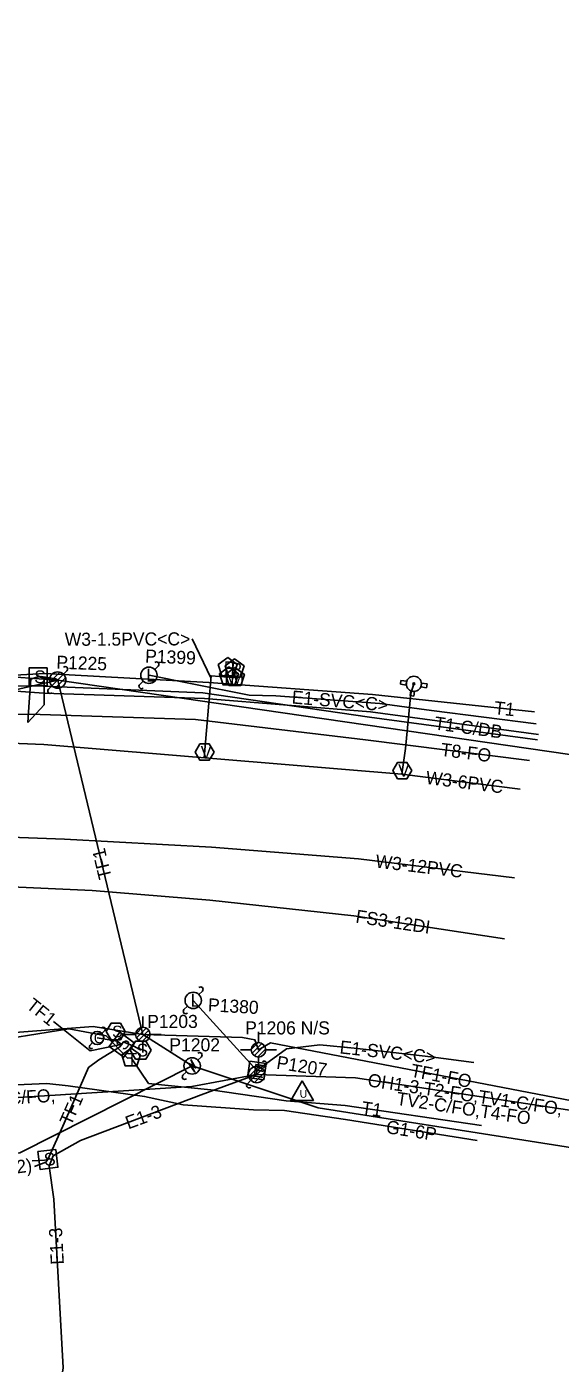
# Model space of a CAD drawing. Extents: x 2336688 to 2352634, y 362473 to 369571.
# Drawn here: x 2352182.9 to 2352345.9, y 368798.3 to 369206.7 of the extents above; entities that cross this region are included whole.
import ezdxf

# ---------------------------------------------------------------- set-up
doc = ezdxf.new("R2010")
doc.units = 0
for name, color, linetype in [('RD_EX_DV_Prop', 7, 'Continuous'), ('RD_EX_DV_TX_Prop', 7, 'Continuous'), ('RD_EX_RW', 7, 'Continuous'), ('RD_EX_RW_TX', 7, 'Continuous'), ('RD_HC_CL_Rel', 7, 'Continuous'), ('RD_HC_Data_Tic', 7, 'Continuous'), ('RD_PD_CstnLmt', 7, 'Continuous'), ('RD_PD_Final_TrvlWay', 7, 'Continuous'), ('RD_PD_FOC', 7, 'Continuous'), ('RD_PD_PatLn2', 7, 'Continuous'), ('RD_PD_PatLn3', 7, 'Continuous'), ('RD_PD_PatLn4', 7, 'Continuous'), ('RD_SHT_ShtClip', 7, 'Continuous'), ('RD_Sketch1', 7, 'Continuous'), ('RD_Sketch2', 7, 'Continuous'), ('RD_Sketch5', 7, 'Continuous'), ('RD_Sketch8', 7, 'Continuous')]:
    doc.layers.add(name, color=color, linetype=linetype)

msp = doc.modelspace()

# ---------------------------------------------------------------- linework, layer by layer
at = {"layer": 'RD_EX_RW_TX'}
for points in [[(2352017.22, 369198.89), (2352037.02, 369199.92), (2352057.29, 369203.53), (2352058.07, 369204.44), (2352059.01, 369204.47), (2352060.05, 369204.49), (2352061.29, 369203.9), (2352068.47, 369206.66), (2352070.73, 369196.74), (2352081.19, 369147.72), (2352093.25, 369098.87), (2352105.47, 369036.02), (2352109, 369016.44), (2352109.72, 369006.36), (2352146.03, 369006.1), (2352188.1, 369003.03), (2352237.18, 369001.37), (2352287.91, 368997.38), (2352339.27, 368990.42)], [(2352338.07, 368997.32), (2352288.54, 369002.61), (2352238.52, 369006.32), (2352188.44, 369009.03), (2352146.1, 369006.66), (2352112.83, 369007.85), (2352101.04, 369009.02), (2352100.18, 369013.02), (2352099.24, 369013.18), (2352099.24, 369013.18), (2352097.56, 369004.44), (2352066.15, 368999.94), (2352042.65, 368996), (2351987.9, 368984.55), (2351939.24, 368974.38), (2351880.64, 368964.81), (2351835.05, 368955.54), (2351792.2, 368945.42), (2351768.45, 368940.51), (2351765.56, 368959.31), (2351765.09, 368961.33)], [(2351880.81, 368963.77), (2351939.3, 368973.2), (2351988.46, 368983.33), (2352042.97, 368994.86), (2352066.53, 368998.78), (2352097.52, 369003.45), (2352112.86, 369004.95), (2352145.97, 369005.39), (2352187.91, 369005.14), (2352236.72, 369003.16), (2352287.61, 368995.73), (2352338.92, 368988.74)], [(2351885, 368956.88), (2351939.56, 368969.89), (2351988.67, 368980.31), (2352043.04, 368991.24), (2352066.63, 368994.3), (2352086.86, 368995.79), (2352106.62, 368995.87), (2352143.1, 368996.58), (2352187.05, 368996.47), (2352234.49, 368995.02), (2352286.43, 368988.83), (2352336.53, 368982.42)], [(2351854.2, 368855.12), (2351907.65, 368859.27), (2351954.44, 368863.43), (2352008.74, 368870.56), (2352052.2, 368876.14), (2352056.52, 368876.05), (2352074.96, 368878.4), (2352092.6, 368880.26), (2352100.36, 368883.74), (2352107.85, 368885.7), (2352121.63, 368887.01), (2352147.59, 368892.36), (2352167.89, 368895.99), (2352195.79, 368900.53), (2352207.22, 368898.3), (2352213.66, 368891.52), (2352214.78, 368891.59), (2352220.15, 368883.78), (2352239.13, 368881.83), (2352262.16, 368878.52), (2352280.21, 368877.05), (2352321.83, 368870.98)]]:
    msp.add_lwpolyline(points, dxfattribs=at)
msp.add_lwpolyline([(2352214.78, 368894.59), (2352211.92, 368892.51), (2352213.01, 368889.16), (2352216.54, 368889.16), (2352217.63, 368892.51)], close=True, dxfattribs=at)
at = {"layer": 'RD_HC_CL_Rel'}
msp.add_lwpolyline([(2351856.12, 368845.07), (2351908.31, 368852.47), (2351954.47, 368856.39), (2351989.24, 368859.76), (2352009.1, 368863.3), (2352075.82, 368872.25), (2352088.74, 368873.22), (2352101.35, 368874.84), (2352111.2, 368876.2), (2352126.61, 368879.82), (2352147.61, 368881.9), (2352189.06, 368883.81), (2352195.59, 368883.03), (2352218.93, 368879.85), (2352230.72, 368877.21), (2352252.22, 368875.78), (2352261.65, 368875.52), (2352280.31, 368872.79), (2352320.53, 368866.38)], dxfattribs=at)
at = {"layer": 'RD_HC_Data_Tic'}
for p, q in [((2352189.96, 369006.41), (2352193.03, 369009.47)), ((2352190.61, 369005.29), (2352194.15, 369008.82)), ((2352194.15, 369008.82), (2352195.21, 369009.88)), ((2352222.02, 369010.27), (2352223.08, 369011.33)), ((2352189.55, 369004.23), (2352190.61, 369005.29)), ((2352191.73, 369004.64), (2352194.79, 369007.7)), ((2352217.42, 369005.68), (2352218.48, 369006.74)), ((2352235.53, 368910.94), (2352236.59, 368912.01)), ((2352230.94, 368906.35), (2352232, 368907.41)), ((2352218.4, 368904.25), (2352218.4, 368900.96)), ((2352205.87, 368899.1), (2352206.72, 368899.95)), ((2352212.88, 368898.74), (2352216.19, 368898.74)), ((2352216.19, 368898.88), (2352218.27, 368900.96)), ((2352216.44, 368897.71), (2352219.44, 368900.71)), ((2352217.1, 368896.96), (2352220.2, 368900.05)), ((2352218.11, 368896.55), (2352220.6, 368899.04)), ((2352220.62, 368898.75), (2352223.93, 368898.75)), ((2352253.71, 368899.56), (2352253.71, 368896.27)), ((2352202.19, 368895.42), (2352203.04, 368896.27)), ((2352218.4, 368896.53), (2352218.4, 368893.25)), ((2352248.18, 368894.05), (2352251.49, 368894.05)), ((2352251.5, 368894.19), (2352253.58, 368896.27)), ((2352251.75, 368893.02), (2352254.74, 368896.02)), ((2352252.4, 368892.27), (2352255.5, 368895.36)), ((2352253.41, 368891.86), (2352255.91, 368894.36)), ((2352255.93, 368894.06), (2352259.24, 368894.07)), ((2352235.22, 368890.91), (2352236.28, 368891.97)), ((2352253.71, 368891.84), (2352253.71, 368888.56)), ((2352230.62, 368886.31), (2352231.68, 368887.37)), ((2352250.72, 368885.87), (2352253.78, 368888.94)), ((2352251.37, 368884.75), (2352254.9, 368888.29)), ((2352252.49, 368884.11), (2352255.55, 368887.17)), ((2352254.9, 368888.29), (2352255.96, 368889.35)), ((2352250.31, 368883.69), (2352251.37, 368884.75))]:
    msp.add_line(p, q, dxfattribs=at)
msp.add_lwpolyline([(2352233.06, 368891.15), (2352233.88, 368889.14), (2352232.43, 368889.94), (2352234.3, 368887.26), (2352234.3, 368887.26), (2352233.1, 368889.35), (2352234.48, 368888.55)], close=True, dxfattribs=at)
for centre, radius in [((2352192.38, 369007.05), 2.5), ((2352220.25, 369008.51), 2.5), ((2352233.76, 368909.18), 2.5), ((2352204.46, 368897.69), 2), ((2352218.4, 368898.75), 2.22), ((2352253.71, 368894.06), 2.22), ((2352233.45, 368889.14), 2.5), ((2352253.13, 368886.52), 2.5)]:
    msp.add_circle(centre, radius, dxfattribs=at)
for centre, radius, start, end in [((2352222.55, 369011.86), 0.75, 315, 135), ((2352194.68, 369010.41), 0.75, 315, 135), ((2352190.08, 369003.7), 0.75, 135, 315), ((2352217.95, 369005.15), 0.75, 135, 315), ((2352236.06, 368912.54), 0.75, 315, 135), ((2352231.47, 368905.82), 0.75, 135, 315), ((2352206.3, 368900.37), 0.6, 315, 135), ((2352202.62, 368895), 0.6, 135, 315), ((2352235.75, 368892.5), 0.75, 315, 135), ((2352255.43, 368889.88), 0.75, 315, 135), ((2352231.15, 368885.78), 0.75, 135, 315), ((2352250.84, 368883.16), 0.75, 135, 315)]:
    msp.add_arc(centre, radius, start, end, dxfattribs=at)
at = {"layer": 'RD_PD_CstnLmt'}
msp.add_line((2352233.4, 369019.65), (2352239.15, 369007.75), dxfattribs=at)
at = {"layer": 'RD_PD_Final_TrvlWay'}
for points in [[(2352220.29, 369008.57), (2352233.42, 369005.94), (2352250.85, 369002.45), (2352259.02, 369002.26), (2352290.75, 368999.87), (2352306.52, 368997.78), (2352338.57, 368993.64)], [(2352253.22, 368887.73), (2352233.76, 368909.18), (2352233.81, 368909.18)], [(2352218.4, 368898.75), (2352248.79, 368897.87), (2352252.62, 368897.13), (2352253.71, 368894.06), (2352257.36, 368896.22), (2352357.47, 368876.97), (2352386.01, 368866.51)], [(2352253.13, 368886.52), (2352253.22, 368887.73), (2352262.26, 368894.32), (2352272.48, 368895.58), (2352282.96, 368894.53), (2352294.85, 368893.28), (2352306.35, 368891.96), (2352319.46, 368890.19)], [(2352253.13, 368886.52), (2352236.2, 368880.33), (2352199.36, 368866.35), (2352190.99, 368861.65), (2352189.74, 368858.57), (2352191.19, 368848.42), (2352194.01, 368796.93), (2352186.25, 368745.32), (2352172.04, 368697.96), (2352173.22, 368647.74), (2352174.91, 368598.79), (2352184.51, 368549.35), (2352193.88, 368501.9), (2352208.42, 368452.8), (2352218.56, 368402.62)], [(2352253.13, 368886.52), (2352283.32, 368885.51), (2352356.87, 368874.44), (2352386.01, 368866.51)]]:
    msp.add_lwpolyline(points, dxfattribs=at)
msp.add_lwpolyline([(2352256.06, 368889.84), (2352251.11, 368890.57), (2352250.38, 368885.63), (2352255.32, 368884.89)], close=True, dxfattribs=at)
at = {"layer": 'RD_PD_FOC'}
for p, q in [((2352183.25, 368994.07), (2352183.67, 369000.32)), ((2352188.28, 368999.49), (2352183.25, 368994.07))]:
    msp.add_line(p, q, dxfattribs=at)
at = {"layer": 'RD_PD_PatLn3'}
msp.add_lwpolyline([(2352267.05, 368884.63), (2352263.58, 368878.63), (2352270.51, 368878.63)], close=True, dxfattribs=at)
at = {"layer": 'RD_SHT_ShtClip'}
for p, q in [((2352192.38, 369007.05), (2352586.08, 368949.9)), ((2352192.38, 369007.05), (2352218.4, 368898.75)), ((2352218.4, 368898.75), (2352233.45, 368889.14))]:
    msp.add_line(p, q, dxfattribs=at)
for points in [[(2352088.13, 369009.76), (2352108.15, 369010.14), (2352172.41, 369008.48), (2352192.38, 369007.05)], [(2352192.38, 369007.05), (2352172.65, 369002.58), (2352092.75, 368996.67), (2352072.58, 368998.19)], [(2352091.68, 368889.02), (2352106.36, 368893.74), (2352203.18, 368901.17), (2352218.4, 368898.75)], [(2351832.35, 368849.22), (2351889.18, 368833.54), (2352180.82, 368862.57), (2352233.45, 368889.14)], [(2352105.46, 368877.27), (2352125.58, 368876.07), (2352233.33, 368882.82), (2352253.13, 368886.52)], [(2352233.45, 368889.14), (2352271.93, 368876.31), (2352518.65, 368837.57), (2352559.21, 368838)]]:
    msp.add_lwpolyline(points, dxfattribs=at)
at = {"layer": 'RD_Sketch2'}
for p, q in [((2352297.19, 369006.92), (2352297.04, 369005.77)), ((2352297.04, 369005.77), (2352298.88, 369005.53)), ((2352298.99, 369006.68), (2352297.19, 369006.92)), ((2352303.27, 369004.95), (2352305.06, 369004.71)), ((2352305.21, 369005.86), (2352303.47, 369006.09)), ((2352305.06, 369004.71), (2352305.21, 369005.86)), ((2352300.25, 369003.77), (2352300.06, 369002.29)), ((2352300.06, 369002.29), (2352301.2, 369002.14)), ((2352301.2, 369002.14), (2352301.39, 369003.6))]:
    msp.add_line(p, q, dxfattribs=at)
for points in [[(2352244.3, 369013.9), (2352241.4, 369011.79), (2352242.51, 369008.38), (2352246.09, 369008.38), (2352247.2, 369011.79)], [(2352246.4, 369013.48), (2352243.5, 369011.37), (2352244.61, 369007.96), (2352248.19, 369007.96), (2352249.3, 369011.37)], [(2352244.67, 369011.07), (2352241.77, 369008.96), (2352242.88, 369005.55), (2352246.46, 369005.55), (2352247.57, 369008.96)], [(2352246.5, 369010.87), (2352243.6, 369008.77), (2352244.71, 369005.36), (2352248.29, 369005.36), (2352249.4, 369008.77)], [(2352240.14, 368985.03), (2352238.69, 368987.53), (2352235.81, 368987.53), (2352234.36, 368985.03), (2352235.81, 368982.53), (2352238.69, 368982.53)], [(2352300.51, 368979.38), (2352299.07, 368981.87), (2352296.18, 368981.87), (2352294.74, 368979.38), (2352296.18, 368976.88), (2352299.07, 368976.88)]]:
    msp.add_lwpolyline(points, close=True, dxfattribs=at)
for points in [[(2352237.11, 368983.31), (2352239.2, 369008.35), (2352244.33, 369007.93)], [(2352297.48, 368978.27), (2352298.57, 368986.11), (2352300.25, 369002.94), (2352301.17, 369005.9)], [(2352089.34, 368987.1), (2352123.62, 368989.01), (2352145.53, 368989.09), (2352188.15, 368987.39), (2352297.48, 368978.27), (2352333.69, 368973.72)], [(2352331.96, 368946.65), (2352284.3, 368952.4), (2352239.4, 368955.94), (2352194.47, 368958.42), (2352147.57, 368960.14), (2352120.89, 368957.46), (2352095.02, 368954.62), (2352046.17, 368949), (2351993.84, 368939.17), (2351944.25, 368929.23), (2351897.87, 368918.99), (2351839.37, 368906.5)]]:
    msp.add_lwpolyline(points, dxfattribs=at)
for radius in [2.31, 0.289]:
    msp.add_circle((2352301.17, 369005.9), radius, dxfattribs=at)
for start, end in [(160.1572, 189.1335), (335.8109, 4.7872), (246.7177, 275.6849)]:
    msp.add_arc((2352301.17, 369005.9), 2.31, start, end, dxfattribs=at)
at = {"layer": 'RD_Sketch5'}
msp.add_lwpolyline([(2351852.53, 368877.54), (2351904.23, 368891.75), (2351948.35, 368906.63), (2351997.09, 368925.32), (2352048.14, 368938.94), (2352097.32, 368947.53), (2352202.88, 368942.76), (2352238.87, 368939.78), (2352282.85, 368935.04), (2352328.83, 368928.03)], dxfattribs=at)
at = {"layer": 'RD_Sketch8'}
for points in [[(2352189.17, 369010.79), (2352183.67, 369010.79), (2352183.67, 369005.29), (2352189.17, 369005.29)], [(2352212.99, 368899.67), (2352211.55, 368902.17), (2352208.66, 368902.17), (2352207.22, 368899.67), (2352208.66, 368897.17), (2352211.55, 368897.17)], [(2352211.33, 368899.49), (2352208.09, 368895.05), (2352212.53, 368891.81), (2352215.77, 368896.25)], [(2352220.9, 368893.98), (2352219.32, 368896.73), (2352216.14, 368896.73), (2352214.55, 368893.98), (2352216.14, 368891.23), (2352219.32, 368891.23)], [(2352191.79, 368863.65), (2352186.33, 368862.99), (2352186.99, 368857.54), (2352192.45, 368858.2)]]:
    msp.add_lwpolyline(points, close=True, dxfattribs=at)
for points in [[(2352183.67, 369000.32), (2352184.15, 369007.31), (2352185.34, 369007.72), (2352186.42, 369008.04), (2352187.3, 369008.16), (2352191.83, 369007.38), (2352192.38, 369007.05)], [(2352192.38, 369007.05), (2352191.48, 369006.87), (2352187.5, 369007.96), (2352186.42, 369008.04), (2352187.56, 369007.85), (2352188.19, 369007.64), (2352188.28, 368999.49)], [(2352191.07, 368902.71), (2352202.29, 368893.78), (2352211.23, 368895.59), (2352211.93, 368895.65)], [(2352211.93, 368895.65), (2352210.51, 368896.7), (2352204.46, 368897.69)], [(2352189.39, 368860.6), (2352194.32, 368871.67), (2352201.81, 368888.7), (2352204.98, 368890.98), (2352211.23, 368894.87), (2352211.93, 368895.65), (2352212.42, 368896.46), (2352215.84, 368895.09), (2352217.73, 368893.98)], [(2352189.39, 368860.6), (2352188.29, 368860.39), (2352184.6, 368860.12)], [(2352189.39, 368860.6), (2352188.7, 368859.73), (2352185.32, 368858.37)]]:
    msp.add_lwpolyline(points, dxfattribs=at)

# ---------------------------------------------------------------- texts
at = {"layer": 'RD_EX_DV_Prop'}
for s, rotation, p in [('E1-SVC<C>', 355.2392, (2352263.76, 368999.89)), ('E1-SVC<C>', 353.6676, (2352278.37, 368892.98)), ('E1-3', 20.0885, (2352213.94, 368869.74)), ('E1-3', 93.1292, (2352194.28, 368828.54))]:
    msp.add_text(s, height=4, rotation=rotation, dxfattribs=at).set_placement(p)
at = {"layer": 'RD_EX_DV_TX_Prop'}
for s, rotation, p in [('P1399', 357.6826, (2352219.02, 369012.41)), ('P1225', 358.0615, (2352191.91, 369010.52)), ('P1380', 356.8165, (2352238.19, 368905.85)), ('P1203', 360, (2352219.7, 368900.74)), ('P1206 N/S', 360, (2352249.64, 368898.77)), ('P1202', 360, (2352226.49, 368893.6)), ('P1207', 351.0775, (2352259.02, 368888.33))]:
    msp.add_text(s, height=4, rotation=rotation, dxfattribs=at).set_placement(p)
at = {"layer": 'RD_EX_RW'}
for s, rotation, p in [('T1', 353.9079, (2352325.57, 368996.64)), ('T1-C/DB', 352.2861, (2352307.26, 368991.98)), ('T8-FO', 352.7135, (2352309.18, 368983.91)), ('T1', 351.7013, (2352284.96, 368874.44))]:
    msp.add_text(s, height=4, rotation=rotation, dxfattribs=at).set_placement(p)
at = {"layer": 'RD_EX_RW_TX'}
msp.add_text('T', height=3.75, dxfattribs=at).set_placement((2352213.55, 368889.36))
at = {"layer": 'RD_HC_Data_Tic'}
for p in [(2352219.44, 369006.57), (2352232.95, 368907.24)]:
    msp.add_text('L', height=4, rotation=360, dxfattribs=at).set_placement(p)
msp.add_text('O', height=3.2, dxfattribs=at).set_placement((2352203.42, 368896.08))
at = {"layer": 'RD_PD_CstnLmt'}
for s, rotation, p in [('W3-1.5PVC<C>', 0.2145, (2352194.53, 369017.5)), ('W3-6PVC', 352.8325, (2352304.64, 368975.35)), ('W3-12PVC', 353.1236, (2352289.28, 368949.79))]:
    msp.add_text(s, height=4, rotation=rotation, dxfattribs=at).set_placement(p)
at = {"layer": 'RD_PD_Final_TrvlWay'}
msp.add_text('E', height=4, rotation=351.5521, dxfattribs=at).set_placement((2352251.72, 368885.93))
at = {"layer": 'RD_PD_FOC'}
for s, rotation, p in [('TF1', 321.4516, (2352182.5, 368907.04)), ('TF1', 66.2546, (2352196.46, 368870.66)), ('TF1(2)', 6.8932, (2352168.8, 368854.94))]:
    msp.add_text(s, height=4, rotation=rotation, dxfattribs=at).set_placement(p)
at = {"layer": 'RD_PD_PatLn2'}
msp.add_text('G1-6P', height=4, rotation=350.9357, dxfattribs=at).set_placement((2352292.48, 368868.65))
at = {"layer": 'RD_PD_PatLn3'}
msp.add_text('U', height=2.4, dxfattribs=at).set_placement((2352266.29, 368879.43))
at = {"layer": 'RD_PD_PatLn4'}
for s, rotation, p in [('TF1', 103.5123, (2352208.93, 368946.73)), ('TF1-FO', 349.1142, (2352299.95, 368885.92)), ('OH1-3,T2-FO,TV1-C/FO,', 351.4461, (2352286.89, 368882.94)), ('OH1-3,T2-FO,TV1-C/FO,', 3.6009, (2352131.83, 368874.45)), ('TV2-C/FO,T4-FO', 351.4461, (2352295.65, 368877.3))]:
    msp.add_text(s, height=4, rotation=rotation, dxfattribs=at).set_placement(p)
at = {"layer": 'RD_Sketch1'}
msp.add_text('FS3-12DI', height=4, rotation=351.3279, dxfattribs=at).set_placement((2352283.2, 368932.96))
at = {"layer": 'RD_Sketch2'}
for p in [(2352243.15, 369008.97), (2352245.25, 369008.56)]:
    msp.add_text('P', height=3.75, rotation=360, dxfattribs=at).set_placement(p)
for s, p in [('M', (2352243.3, 369006.02)), ('M', (2352245.13, 369005.83)), ('V', (2352236.04, 368983.16)), ('V', (2352296.41, 368977.5))]:
    msp.add_text(s, height=3.75, dxfattribs=at).set_placement(p)
at = {"layer": 'RD_Sketch8'}
for height, p in [(3.89, (2352185.22, 369006.09)), (3.53, (2352209.02, 368897.9)), (3.89, (2352216.53, 368892.04))]:
    msp.add_text('S', height=height, dxfattribs=at).set_placement(p)
for rotation, p in [(53.8729, (2352212.8, 368893.54)), (6.8932, (2352188.44, 368858.52))]:
    msp.add_text('S', height=3.89, rotation=rotation, dxfattribs=at).set_placement(p)

doc.saveas('drawing.dxf')
